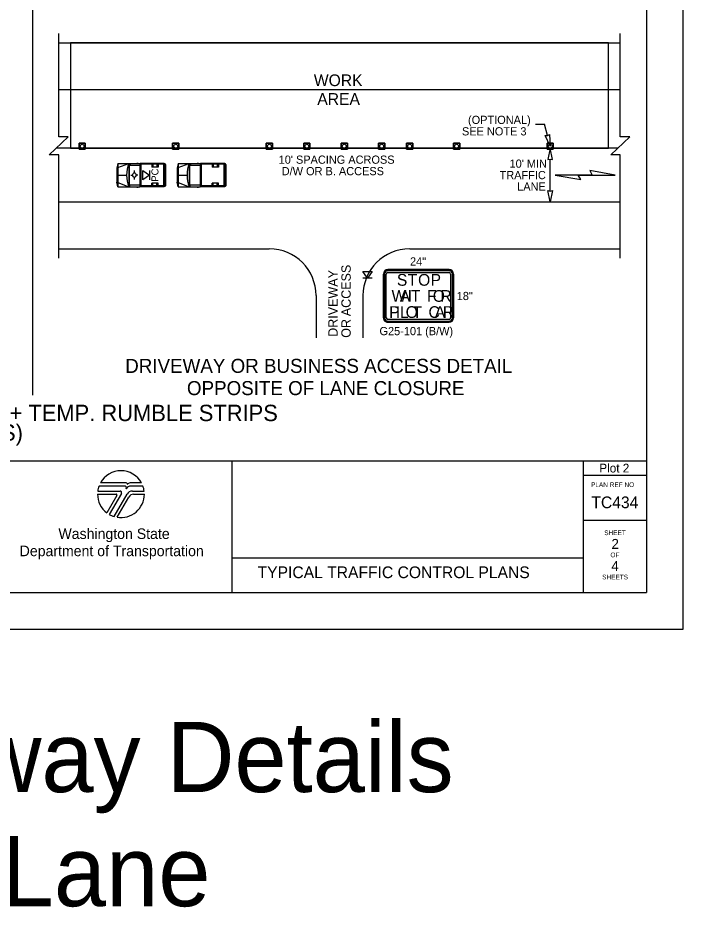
# Model space of a CAD drawing. Extents: x 99999.1 to 100095.7, y 99995 to 100010.7.
# Drawn here: x 100030.38 to 100036.06, y 99997.31 to 100004.91 of the extents above; entities that cross this region are included whole.
import ezdxf

# ---------------------------------------------------------------- set-up
doc = ezdxf.new("R2010")
doc.units = 0
for name, color, linetype in [('RD_ED_DrivewayEdge', 7, 'Continuous'), ('RD_ED_ShoulderPavedEdge', 7, 'Continuous'), ('RD_MK_LineEdgeWhite', 7, 'Continuous'), ('RD_MK_LineSkipCenter', 7, 'Continuous'), ('SH_DE_DetailHeading1Text', 7, 'Continuous'), ('SH_DE_DetailHeading2Text', 7, 'Continuous'), ('SH_GI_PlotLimits', 7, 'Continuous'), ('SH_GI_SheetBorder', 7, 'Continuous'), ('SH_GI_SheetLocationText', 7, 'Continuous'), ('SH_GI_SheetTextInCells', 7, 'Continuous'), ('SH_GI_TitleBlockText', 7, 'Continuous'), ('SH_GI_WSDOTLogo', 7, 'Continuous'), ('TR_SN_ConstructionSigns', 7, 'Continuous'), ('TR_WZ_MotoristVehicle', 7, 'Continuous'), ('TR_WZ_PortableSignMountBlk-Wht', 7, 'Continuous'), ('TR_WZ_TrafficCone', 7, 'Continuous'), ('TR_WZ_WorkAreaLabel', 7, 'Continuous'), ('TR_WZ_WorkZoneDetails', 7, 'Continuous'), ('TR_WZ_WorkZoneTextCurrent', 7, 'Continuous')]:
    doc.layers.add(name, color=color, linetype=linetype)

msp = doc.modelspace()

# ---------------------------------------------------------------- linework, layer by layer
at = {"layer": 'RD_ED_DrivewayEdge'}
for p, q in [((100032.925, 100002.5359), (100032.925, 100002.1759)), ((100033.325, 100002.5359), (100033.325, 100002.1759))]:
    msp.add_line(p, q, dxfattribs=at)
for centre, start, end in [((100032.525, 100002.5359), 0, 90), ((100033.725, 100002.5359), 90, 180)]:
    msp.add_arc(centre, 0.4, start, end, dxfattribs=at)
at = {"layer": 'RD_ED_ShoulderPavedEdge'}
for p, q in [((100030.725, 100004.6959), (100035.525, 100004.6959)), ((100030.725, 100002.9359), (100032.525, 100002.9359)), ((100033.725, 100002.9359), (100035.525, 100002.9359))]:
    msp.add_line(p, q, dxfattribs=at)
at = {"layer": 'RD_MK_LineEdgeWhite'}
for p, q in [((100030.725, 100004.2959), (100035.525, 100004.2959)), ((100030.725, 100003.3359), (100035.525, 100003.3359))]:
    msp.add_line(p, q, dxfattribs=at)
at = {"layer": 'RD_MK_LineSkipCenter'}
msp.add_lwpolyline([(100035.5043, 100003.7959), (100030.7043, 100003.7959)], dxfattribs=at)
at = {"layer": 'SH_GI_PlotLimits'}
msp.add_lwpolyline([(100019.0625, 99999.6875), (100036.0625, 99999.6875), (100036.0625, 100010.6875), (100019.0625, 100010.6875)], close=True, dxfattribs=at)
at = {"layer": 'SH_GI_SheetBorder'}
for p, q in [((100035.75, 100010.375), (100035.75, 100000)), ((100020, 100001.1259), (100035.75, 100001.1259)), ((100032.2055, 100001.1259), (100032.2055, 100000)), ((100035.2079, 100001.1259), (100035.2079, 100000)), ((100035.2079, 100001.0008), (100035.75, 100001.0008)), ((100035.2079, 100000.6176), (100035.75, 100000.6176)), ((100032.2055, 100000.2955), (100035.2079, 100000.2955)), ((100020, 100000), (100035.75, 100000))]:
    msp.add_line(p, q, dxfattribs=at)
at = {"layer": 'SH_GI_WSDOTLogo'}
for p, q in [((100031.2894, 100000.9094), (100031.0697, 100000.9094)), ((100031.303, 100000.9354), (100031.0815, 100000.9354)), ((100031.433, 100000.9354), (100031.3351, 100000.9354)), ((100031.343, 100000.9094), (100031.3429, 100000.9094)), ((100031.4448, 100000.9094), (100031.343, 100000.9094)), ((100031.0572, 100000.84), (100031.2148, 100000.84)), ((100031.059, 100000.8661), (100031.2496, 100000.8661)), ((100031.222, 100000.8277), (100031.1364, 100000.6807)), ((100031.261, 100000.8464), (100031.1567, 100000.6672)), ((100031.1989, 100000.6487), (100031.3089, 100000.839)), ((100031.3558, 100000.8661), (100031.4555, 100000.8661)), ((100031.3655, 100000.8394), (100031.4572, 100000.8394)), ((100031.2244, 100000.6428), (100031.3242, 100000.8156))]:
    msp.add_line(p, q, dxfattribs=at)
for centre, radius, start, end in [((100031.2572, 100000.84), 0.2, 28.47865, 151.53204), ((100031.2572, 100000.84), 0.2, 159.69598, 172.50569), ((100031.2894, 100000.8946), 0.0148, 327.8418, 89.99855), ((100031.3429, 100000.861), 0.0484, 89.99529, 147.82376), ((100031.303, 100000.9263), 0.00903, 329.87418, 90.00328), ((100031.3352, 100000.9066), 0.0287, 90.00721, 148.16763), ((100031.2572, 100000.84), 0.2, 7.49431, 20.29406), ((100031.2572, 100000.84), 0.2, 179.99864, 232.84327), ((100031.2149, 100000.8318), 0.0082, 329.74356, 90), ((100031.2572, 100000.84), 0.2, 260.54554, 359.80857), ((100031.2497, 100000.853), 0.0131, 329.76834, 90), ((100031.3558, 100000.8119), 0.0542, 90, 149.99738), ((100031.3654, 100000.7918), 0.0476, 90, 150.05432), ((100031.2572, 100000.84), 0.2, 239.79292, 253.0448)]:
    msp.add_arc(centre, radius, start, end, dxfattribs=at)
at = {"layer": 'TR_SN_ConstructionSigns'}
for p, q in [((100033.5, 100002.3456), (100033.5, 100002.7206)), ((100033.5, 100002.7206), (100033.5, 100002.3456)), ((100033.5094, 100002.7206), (100033.5094, 100002.3456)), ((100033.525, 100002.3456), (100033.525, 100002.7206)), ((100033.5375, 100002.7581), (100034.0625, 100002.7581)), ((100034.0625, 100002.7581), (100033.5375, 100002.7581)), ((100034.0625, 100002.7488), (100033.5375, 100002.7488)), ((100033.5375, 100002.7331), (100034.0625, 100002.7331)), ((100034.075, 100002.7206), (100034.075, 100002.3456)), ((100034.0906, 100002.3456), (100034.0906, 100002.7206)), ((100034.1, 100002.7206), (100034.1, 100002.3456)), ((100034.1, 100002.3456), (100034.1, 100002.7206)), ((100034.0625, 100002.3331), (100033.5375, 100002.3331)), ((100033.5375, 100002.3175), (100034.0625, 100002.3175)), ((100034.0625, 100002.3081), (100033.5375, 100002.3081)), ((100033.5375, 100002.3081), (100034.0625, 100002.3081))]:
    msp.add_line(p, q, dxfattribs=at)
for centre, radius, start, end in [((100033.5375, 100002.7206), 0.0375, 90, 180), ((100033.5375, 100002.7206), 0.0375, 90, 180), ((100033.5375, 100002.7206), 0.0281, 90, 180.00001), ((100033.5375, 100002.7206), 0.0125, 90, 180.00001), ((100034.0625, 100002.7206), 0.0375, 0, 90), ((100034.0625, 100002.7206), 0.0375, 0, 90), ((100034.0625, 100002.7206), 0.0281, 0, 90), ((100034.0625, 100002.7206), 0.0125, 0, 90), ((100033.5375, 100002.3456), 0.0375, 180, 270.00001), ((100033.5375, 100002.3456), 0.0375, 180, 270.00001), ((100033.5375, 100002.3456), 0.0281, 180.00001, 270), ((100033.5375, 100002.3456), 0.0125, 180.00001, 270), ((100034.0625, 100002.3456), 0.0375, 270.00001, 0.00001), ((100034.0625, 100002.3456), 0.0375, 270.00001, 0.00001), ((100034.0625, 100002.3456), 0.0281, 270, 0.00001), ((100034.0625, 100002.3456), 0.0125, 270, 0.00001)]:
    msp.add_arc(centre, radius, start, end, dxfattribs=at)
at = {"layer": 'TR_WZ_MotoristVehicle'}
for p, q in [((100031.23, 100003.6659), (100031.2207, 100003.6255)), ((100031.23, 100003.6659), (100031.23, 100003.4659)), ((100031.23, 100003.6659), (100031.4189, 100003.6659)), ((100031.23, 100003.6293), (100031.3245, 100003.6659)), ((100031.3245, 100003.6659), (100031.3245, 100003.4659)), ((100031.3262, 100003.6659), (100031.3262, 100003.4659)), ((100031.3262, 100003.6659), (100031.3382, 100003.6504)), ((100031.3262, 100003.6504), (100031.4189, 100003.6504)), ((100031.3932, 100003.6687), (100031.4045, 100003.6687)), ((100031.4189, 100003.6659), (100031.4189, 100003.4659)), ((100031.6274, 100003.6659), (100031.4217, 100003.6659)), ((100031.4217, 100003.6659), (100031.4217, 100003.4659)), ((100031.6215, 100003.6579), (100031.4275, 100003.6579)), ((100031.4275, 100003.6579), (100031.4275, 100003.4739)), ((100031.5202, 100003.6579), (100031.5202, 100003.6349)), ((100031.5752, 100003.6349), (100031.5202, 100003.6349)), ((100031.5302, 100003.6579), (100031.5302, 100003.6349)), ((100031.5642, 100003.6579), (100031.5642, 100003.6349)), ((100031.5752, 100003.6579), (100031.5752, 100003.6349)), ((100031.6215, 100003.6579), (100031.6215, 100003.4739)), ((100031.6274, 100003.6659), (100031.6274, 100003.4659)), ((100031.6325, 100003.6626), (100031.6281, 100003.6626)), ((100031.6281, 100003.6626), (100031.6281, 100003.4692)), ((100031.637, 100003.6565), (100031.637, 100003.4753)), ((100031.7463, 100003.6659), (100031.737, 100003.6255)), ((100031.7463, 100003.6659), (100031.7463, 100003.4659)), ((100031.7463, 100003.6659), (100031.9352, 100003.6659)), ((100031.7463, 100003.6293), (100031.8407, 100003.6659)), ((100031.8407, 100003.6659), (100031.8407, 100003.4659)), ((100031.8424, 100003.6659), (100031.8424, 100003.4659)), ((100031.8424, 100003.6659), (100031.8545, 100003.6504)), ((100031.8424, 100003.6504), (100031.9352, 100003.6504)), ((100031.9094, 100003.6687), (100031.9207, 100003.6687)), ((100031.9352, 100003.6659), (100031.9352, 100003.4659)), ((100032.1436, 100003.6659), (100031.9379, 100003.6659)), ((100031.9379, 100003.6659), (100031.9379, 100003.4659)), ((100032.1378, 100003.6579), (100031.9438, 100003.6579)), ((100031.9438, 100003.6579), (100031.9438, 100003.4739)), ((100032.0365, 100003.6579), (100032.0365, 100003.6349)), ((100032.0914, 100003.6349), (100032.0365, 100003.6349)), ((100032.0465, 100003.6579), (100032.0465, 100003.6349)), ((100032.0805, 100003.6579), (100032.0805, 100003.6349)), ((100032.0914, 100003.6579), (100032.0914, 100003.6349)), ((100032.1378, 100003.6579), (100032.1378, 100003.4739)), ((100032.1436, 100003.6659), (100032.1436, 100003.4659)), ((100032.1488, 100003.6626), (100032.1443, 100003.6626)), ((100032.1443, 100003.6626), (100032.1443, 100003.4692)), ((100032.1533, 100003.6565), (100032.1533, 100003.4753)), ((100031.2207, 100003.6255), (100031.2207, 100003.5063)), ((100031.23, 100003.5659), (100031.3059, 100003.5659)), ((100031.3414, 100003.566), (100031.354, 100003.566)), ((100031.3715, 100003.6055), (100031.3715, 100003.5894)), ((100031.3856, 100003.5656), (100031.3856, 100003.5656)), ((100031.4024, 100003.5651), (100031.3875, 100003.5655)), ((100031.637, 100003.58), (100031.6281, 100003.5762)), ((100031.637, 100003.5518), (100031.6281, 100003.5556)), ((100031.6346, 100003.5659), (100031.6305, 100003.5659)), ((100031.6325, 100003.5687), (100031.6325, 100003.5631)), ((100031.737, 100003.6255), (100031.737, 100003.5063)), ((100031.7463, 100003.5659), (100031.8222, 100003.5659)), ((100032.1533, 100003.58), (100032.1443, 100003.5762)), ((100032.1533, 100003.5518), (100032.1443, 100003.5556)), ((100032.1509, 100003.5659), (100032.1467, 100003.5659)), ((100032.1488, 100003.5687), (100032.1488, 100003.5631)), ((100031.23, 100003.4659), (100031.2207, 100003.5063)), ((100031.23, 100003.5025), (100031.3245, 100003.4659)), ((100031.3262, 100003.4814), (100031.4189, 100003.4814)), ((100031.3361, 100003.4814), (100031.3262, 100003.4659)), ((100031.3722, 100003.5274), (100031.3719, 100003.5425)), ((100031.5202, 100003.4739), (100031.5202, 100003.4969)), ((100031.5752, 100003.4969), (100031.5202, 100003.4969)), ((100031.5302, 100003.4739), (100031.5302, 100003.4969)), ((100031.5642, 100003.4739), (100031.5642, 100003.4969)), ((100031.5752, 100003.4739), (100031.5752, 100003.4969)), ((100031.7463, 100003.4659), (100031.737, 100003.5063)), ((100031.7463, 100003.5025), (100031.8407, 100003.4659)), ((100031.8424, 100003.4814), (100031.9352, 100003.4814)), ((100031.8524, 100003.4814), (100031.8424, 100003.4659)), ((100032.0365, 100003.4739), (100032.0365, 100003.4969)), ((100032.0914, 100003.4969), (100032.0365, 100003.4969)), ((100032.0465, 100003.4739), (100032.0465, 100003.4969)), ((100032.0805, 100003.4739), (100032.0805, 100003.4969)), ((100032.0914, 100003.4739), (100032.0914, 100003.4969)), ((100031.23, 100003.4659), (100031.4189, 100003.4659)), ((100031.3932, 100003.4631), (100031.4045, 100003.4631)), ((100031.6274, 100003.4659), (100031.4217, 100003.4659)), ((100031.6215, 100003.4739), (100031.4275, 100003.4739)), ((100031.6325, 100003.4692), (100031.6281, 100003.4692)), ((100031.7463, 100003.4659), (100031.9352, 100003.4659)), ((100031.9094, 100003.4631), (100031.9207, 100003.4631)), ((100032.1436, 100003.4659), (100031.9379, 100003.4659)), ((100032.1378, 100003.4739), (100031.9438, 100003.4739)), ((100032.1488, 100003.4692), (100032.1443, 100003.4692))]:
    msp.add_line(p, q, dxfattribs=at)
for centre, major_axis, start_param, end_param in [((100031.4595, 100003.5659), (0, -0.2099), 4.215667, 5.208926), ((100031.6325, 100003.6565), (0, 0.0061), 4.712389, 6.283185), ((100031.9757, 100003.5659), (0, -0.2099), 4.215667, 5.208926), ((100032.1488, 100003.6565), (0, 0.0061), 4.712389, 6.283185), ((100031.6325, 100003.4753), (0, -0.0061), 0, 1.570796), ((100032.1488, 100003.4753), (0, -0.0061), 0, 1.570796)]:
    msp.add_ellipse(centre, major_axis=major_axis, ratio=0.73155, start_param=start_param, end_param=end_param, dxfattribs=at)
for centre, major_axis in [((100031.3715, 100003.5659), (0, 0.0193)), ((100031.6325, 100003.5659), (0, 0.00282)), ((100032.1488, 100003.5659), (0, 0.00282))]:
    msp.add_ellipse(centre, major_axis=major_axis, ratio=0.73155, dxfattribs=at)
at = {"layer": 'TR_WZ_PortableSignMountBlk-Wht'}
for p, q in [((100031.5013, 100003.6058), (100031.5013, 100003.5258)), ((100033.405, 100002.6859), (100033.325, 100002.6859))]:
    msp.add_line(p, q, dxfattribs=at)
for points in [[(100031.5013, 100003.5659), (100031.4439, 100003.5258), (100031.4439, 100003.6058)], [(100033.3651, 100002.6859), (100033.325, 100002.7434), (100033.405, 100002.7434)]]:
    msp.add_lwpolyline(points, close=True, dxfattribs=at)
at = {"layer": 'TR_WZ_TrafficCone'}
for points in [[(100030.899, 100003.8392), (100030.9524, 100003.8392), (100030.9524, 100003.7859), (100030.899, 100003.7859), (100030.899, 100003.8392)], [(100030.899, 100003.7859), (100030.9524, 100003.7859), (100030.9524, 100003.8392), (100030.899, 100003.8392), (100030.899, 100003.7859)], [(100031.699, 100003.8392), (100031.7524, 100003.8392), (100031.7524, 100003.7859), (100031.699, 100003.7859), (100031.699, 100003.8392)], [(100031.699, 100003.7859), (100031.7524, 100003.7859), (100031.7524, 100003.8392), (100031.699, 100003.8392), (100031.699, 100003.7859)], [(100032.499, 100003.8392), (100032.5524, 100003.8392), (100032.5524, 100003.7859), (100032.499, 100003.7859), (100032.499, 100003.8392)], [(100032.499, 100003.7859), (100032.5524, 100003.7859), (100032.5524, 100003.8392), (100032.499, 100003.8392), (100032.499, 100003.7859)], [(100032.819, 100003.8392), (100032.8723, 100003.8392), (100032.8723, 100003.7859), (100032.819, 100003.7859), (100032.819, 100003.8392)], [(100032.819, 100003.7859), (100032.8723, 100003.7859), (100032.8723, 100003.8392), (100032.819, 100003.8392), (100032.819, 100003.7859)], [(100033.139, 100003.8392), (100033.1923, 100003.8392), (100033.1923, 100003.7859), (100033.139, 100003.7859), (100033.139, 100003.8392)], [(100033.139, 100003.7859), (100033.1923, 100003.7859), (100033.1923, 100003.8392), (100033.139, 100003.8392), (100033.139, 100003.7859)], [(100033.459, 100003.8392), (100033.5123, 100003.8392), (100033.5123, 100003.7859), (100033.459, 100003.7859), (100033.459, 100003.8392)], [(100033.459, 100003.7859), (100033.5123, 100003.7859), (100033.5123, 100003.8392), (100033.459, 100003.8392), (100033.459, 100003.7859)], [(100033.6983, 100003.8392), (100033.7517, 100003.8392), (100033.7517, 100003.7859), (100033.6983, 100003.7859), (100033.6983, 100003.8392)], [(100033.6983, 100003.7859), (100033.7517, 100003.7859), (100033.7517, 100003.8392), (100033.6983, 100003.8392), (100033.6983, 100003.7859)], [(100034.099, 100003.8392), (100034.1524, 100003.8392), (100034.1524, 100003.7859), (100034.099, 100003.7859), (100034.099, 100003.8392)], [(100034.099, 100003.7859), (100034.1524, 100003.7859), (100034.1524, 100003.8392), (100034.099, 100003.8392), (100034.099, 100003.7859)], [(100034.899, 100003.8392), (100034.9524, 100003.8392), (100034.9524, 100003.7859), (100034.899, 100003.7859), (100034.899, 100003.8392)], [(100034.899, 100003.7859), (100034.9524, 100003.7859), (100034.9524, 100003.8392), (100034.899, 100003.8392), (100034.899, 100003.7859)]]:
    msp.add_lwpolyline(points, dxfattribs=at)
for centre in [(100030.9257, 100003.8126), (100031.7257, 100003.8126), (100032.5257, 100003.8126), (100032.8457, 100003.8126), (100033.1657, 100003.8126), (100033.4857, 100003.8126), (100033.725, 100003.8126), (100034.1257, 100003.8126), (100034.9257, 100003.8126)]:
    msp.add_circle(centre, 0.0167, dxfattribs=at)
at = {"layer": 'TR_WZ_WorkZoneDetails'}
for p, q in [((100030.5, 100010.275), (100030.5, 100001.6859)), ((100034.8007, 100004.0006), (100034.8769, 100004.0006)), ((100034.9022, 100003.9033), (100034.8769, 100004.0006)), ((100034.9256, 100003.4296), (100034.9256, 100003.7022)), ((100035.2856, 100003.5659), (100035.0445, 100003.5659)), ((100035.1651, 100003.5659), (100035.4062, 100003.5659)), ((100033.5, 100002.7206), (100033.5, 100002.3456)), ((100034.0625, 100002.7581), (100033.5375, 100002.7581)), ((100034.1, 100002.3456), (100034.1, 100002.7206)), ((100033.5375, 100002.3081), (100034.0625, 100002.3081))]:
    msp.add_line(p, q, dxfattribs=at)
for points in [[(100030.725, 100002.8559), (100030.725, 100003.7385), (100030.645, 100003.7385), (100030.805, 100003.8933), (100030.725, 100003.8933), (100030.725, 100004.7759)], [(100035.525, 100002.8559), (100035.525, 100003.7385), (100035.445, 100003.7385), (100035.605, 100003.8933), (100035.525, 100003.8933), (100035.525, 100004.7759)]]:
    msp.add_lwpolyline(points, dxfattribs=at)
for points in [[(100030.825, 100004.6959), (100030.825, 100003.7959), (100035.425, 100003.7959), (100035.425, 100004.6959)], [(100034.9257, 100003.8126), (100034.8824, 100003.9029), (100034.9022, 100003.9033), (100034.9197, 100003.9125)], [(100034.9257, 100003.7959), (100034.9064, 100003.6976), (100034.9257, 100003.7022), (100034.945, 100003.6976)], [(100034.9685, 100003.5659), (100035.1873, 100003.5273), (100035.1651, 100003.5659)], [(100035.4821, 100003.5659), (100035.2633, 100003.6045), (100035.2856, 100003.5659)], [(100034.9256, 100003.3359), (100034.9064, 100003.4342), (100034.9256, 100003.4296), (100034.9449, 100003.4342)]]:
    msp.add_lwpolyline(points, close=True, dxfattribs=at)
for centre, start, end in [((100033.5375, 100002.7206), 90, 180), ((100034.0625, 100002.7206), 0, 90), ((100033.5375, 100002.3456), 180, 270.00001), ((100034.0625, 100002.3456), 270.00001, 0.00001)]:
    msp.add_arc(centre, 0.0375, start, end, dxfattribs=at)

# ---------------------------------------------------------------- texts
at = {"layer": 'SH_DE_DetailHeading1Text'}
for s, p in [('PILOT CAR OPERATION FOR ALTERNATING 1-LANE, 2-WAY TRAFFIC: AFAD-CONTROLLED + TEMP. RUMBLE STRIPS', (100022.1077, 100001.4639)), ('SHARED BIKE-LANE STRATEGY (HIGHWAYS, 40 MPH OR LESS)', (100024.7084, 100001.2959))]:
    msp.add_text(s, height=0.14, rotation=360, dxfattribs=at).set_placement(p)
at = {"layer": 'SH_DE_DetailHeading2Text'}
for s, p in [('DRIVEWAY OR BUSINESS ACCESS DETAIL', (100031.2936, 100001.8759)), ('OPPOSITE OF LANE CLOSURE', (100031.8211, 100001.6859))]:
    msp.add_text(s, height=0.12, rotation=360, dxfattribs=at).set_placement(p)
at = {"layer": 'SH_GI_SheetBorder'}
msp.add_text('PLAN REF NO', height=0.040032, dxfattribs=at).set_placement((100035.2747, 100000.9008))
at = {"layer": 'SH_GI_SheetLocationText'}
for s, height, p in [('Plot 2', 0.075, (100035.3454, 100001.025)), ('Access & Intersecting Roadway Details', 0.6, (100020.1422, 99998.2946)), ('Shared Bike-Vehicle Lane', 0.6, (100022.7454, 99997.3196))]:
    msp.add_text(s, height=height, dxfattribs=at).set_placement(p)
at = {"layer": 'SH_GI_SheetTextInCells'}
for s, height, p in [('Washington State', 0.090072, (100030.7229, 100000.4571)), ('SHEET', 0.04003, (100035.3877, 100000.4896)), ('Department of Transportation', 0.090072, (100030.3916, 100000.3101)), ('OF', 0.04003, (100035.4406, 100000.3008)), ('SHEETS', 0.04003, (100035.3698, 100000.112))]:
    msp.add_text(s, height=height, dxfattribs=at).set_placement(p)
at = {"layer": 'SH_GI_TitleBlockText'}
for s, height, p in [('TC434', 0.1, (100035.2776, 100000.72)), ('2', 0.085, (100035.4493, 100000.3723)), ('TYPICAL TRAFFIC CONTROL PLANS', 0.1, (100032.4251, 100000.1224)), ('4', 0.085, (100035.4485, 100000.1843))]:
    msp.add_text(s, height=height, dxfattribs=at).set_placement(p)
at = {"layer": 'TR_SN_ConstructionSigns'}
for s, p in [('24"', (100033.7276, 100002.7931)), ('18"', (100034.1269, 100002.4981)), ('G25-101 (B/W)', (100033.4667, 100002.1981))]:
    msp.add_text(s, height=0.07, rotation=360, dxfattribs=at).set_placement(p)
at = {"layer": 'TR_WZ_MotoristVehicle'}
msp.add_text('PC', height=0.06, rotation=90, dxfattribs=at).set_placement((100031.5777, 100003.5099))
at = {"layer": 'TR_WZ_WorkAreaLabel'}
for s, p in [('WORK', (100032.9058, 100004.3259)), ('AREA', (100032.9354, 100004.1659))]:
    msp.add_text(s, height=0.1, dxfattribs=at).set_placement(p)
at = {"layer": 'TR_WZ_WorkZoneDetails'}
for s, p in [('S', (100033.6155, 100002.6206)), ('T', (100033.7075, 100002.6206)), ('O', (100033.7965, 100002.6206)), ('P', (100033.9035, 100002.6206)), ('W', (100033.57, 100002.4831)), ('A', (100033.64, 100002.4831)), ('I', (100033.708, 100002.4831)), ('T', (100033.735, 100002.4831)), ('F', (100033.873, 100002.4831)), ('O', (100033.922, 100002.4831)), ('R', (100033.987, 100002.4831)), ('P', (100033.5495, 100002.3456)), ('I', (100033.6065, 100002.3456)), ('L', (100033.6415, 100002.3456)), ('O', (100033.6905, 100002.3456)), ('T', (100033.7475, 100002.3456)), ('C', (100033.8855, 100002.3456)), ('A', (100033.9395, 100002.3456)), ('R', (100034.0075, 100002.3456))]:
    msp.add_text(s, height=0.1, dxfattribs=at).set_placement(p)
at = {"layer": 'TR_WZ_WorkZoneTextCurrent'}
for s, p in [('(OPTIONAL)', (100034.2233, 100004.0026)), ('SEE NOTE 3', (100034.1716, 100003.9046)), ("10' SPACING ACROSS", (100032.605, 100003.6626)), ('D/W OR B. ACCESS', (100032.6312, 100003.5646)), ("10' MIN", (100034.5783, 100003.6289)), ('TRAFFIC', (100034.4933, 100003.5309)), ('LANE', (100034.6437, 100003.4329))]:
    msp.add_text(s, height=0.07, dxfattribs=at).set_placement(p)
for s, p in [('ACCESS', (100033.221, 100002.3602)), ('DRIVEWAY', (100033.109, 100002.1842)), ('OR', (100033.221, 100002.1759))]:
    msp.add_text(s, height=0.08, rotation=90, dxfattribs=at).set_placement(p)

doc.saveas('drawing.dxf')
